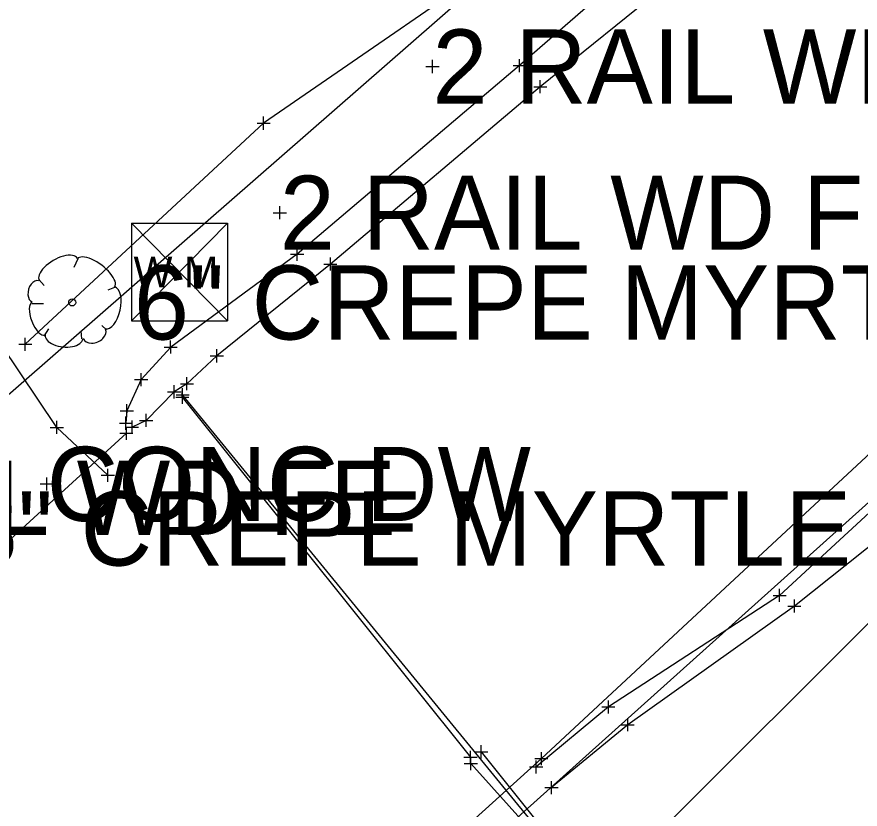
# Model space of a CAD drawing. Extents: x -1 to 1157254, y -1 to 2021979.
# Drawn here: x 1147450.2 to 1147532.2, y 2017383.4 to 2017460.4 of the extents above; entities that cross this region are included whole.
import ezdxf

# ---------------------------------------------------------------- set-up
doc = ezdxf.new("R2010")
doc.units = 0
for name, color, linetype in [('S_BUILDING_ANNOT', 7, 'Continuous'), ('S_CAL_CORNER_ANNOT', 7, 'Continuous'), ('S_CONTOUR_ANNOT', 7, 'Continuous'), ('S_CTL_TABLE', 7, 'Continuous'), ('S_CURB', 7, 'Continuous'), ('S_DITCHLINE', 7, 'Continuous'), ('S_DRIVEWAY_ANNOT', 7, 'Continuous'), ('S_DROP_INLET', 7, 'Continuous'), ('S_DROP_INLET_ANNOT', 7, 'Continuous'), ('S_EDGE_BITUMINOUS_ANNOT', 7, 'Continuous'), ('S_ENV_CONSTRAINT', 7, 'Continuous'), ('S_EXIST_ROW', 7, 'Continuous'), ('S_FENCE', 7, 'Continuous'), ('S_GATE', 7, 'Continuous'), ('S_GATE_ANNOT', 7, 'Continuous')]:
    doc.layers.add(name, color=color, linetype=linetype)

msp = doc.modelspace()

# ---------------------------------------------------------------- linework, layer by layer
at = {"layer": 'S_BUILDING_ANNOT'}
for p, q in [((1147489.991, 2017455.56), (1147491.263, 2017455.563)), ((1147490.628, 2017454.925), (1147490.625, 2017456.198)), ((1147490.627, 2017455.562), (1147490.627, 2017455.562)), ((1147498.452, 2017455.653), (1147499.724, 2017455.656)), ((1147499.089, 2017455.018), (1147499.087, 2017456.291)), ((1147499.088, 2017455.655), (1147499.088, 2017455.655)), ((1147501.104, 2017452.962), (1147501.101, 2017454.235)), ((1147500.466, 2017453.597), (1147501.738, 2017453.6)), ((1147501.102, 2017453.599), (1147501.102, 2017453.599)), ((1147475.788, 2017440.725), (1147475.785, 2017441.997)), ((1147475.15, 2017441.36), (1147476.422, 2017441.362)), ((1147475.786, 2017441.361), (1147475.786, 2017441.361)), ((1147477.48, 2017436.691), (1147477.477, 2017437.963)), ((1147476.842, 2017437.326), (1147478.115, 2017437.328)), ((1147477.478, 2017437.327), (1147477.478, 2017437.327)), ((1147480.702, 2017435.742), (1147480.699, 2017437.014)), ((1147480.064, 2017436.377), (1147481.337, 2017436.379)), ((1147480.7, 2017436.378), (1147480.7, 2017436.378)), ((1147465.183, 2017427.676), (1147465.18, 2017428.949)), ((1147464.546, 2017428.311), (1147465.818, 2017428.314)), ((1147465.182, 2017428.313), (1147465.182, 2017428.313)), ((1147469.669, 2017426.824), (1147469.667, 2017428.097)), ((1147469.032, 2017427.459), (1147470.304, 2017427.462)), ((1147469.668, 2017427.461), (1147469.668, 2017427.461)), ((1147462.312, 2017424.516), (1147462.309, 2017425.789)), ((1147466.764, 2017424.116), (1147466.762, 2017425.389)), ((1147461.674, 2017425.151), (1147462.947, 2017425.154)), ((1147462.311, 2017425.152), (1147462.311, 2017425.152)), ((1147465.522, 2017423.335), (1147465.519, 2017424.608)), ((1147466.127, 2017424.751), (1147467.399, 2017424.754)), ((1147466.763, 2017424.752), (1147466.763, 2017424.752)), ((1147464.885, 2017423.97), (1147466.157, 2017423.973)), ((1147465.521, 2017423.971), (1147465.521, 2017423.971)), ((1147465.705, 2017423.683), (1147466.977, 2017423.686)), ((1147466.315, 2017422.805), (1147466.313, 2017424.078)), ((1147466.342, 2017423.048), (1147466.34, 2017424.321)), ((1147466.341, 2017423.684), (1147466.341, 2017423.684)), ((1147460.925, 2017421.491), (1147460.922, 2017422.764)), ((1147465.678, 2017423.44), (1147466.95, 2017423.443)), ((1147466.314, 2017423.441), (1147466.314, 2017423.441)), ((1147460.287, 2017422.126), (1147461.56, 2017422.129)), ((1147460.924, 2017422.127), (1147460.924, 2017422.127)), ((1147454.117, 2017419.877), (1147454.114, 2017421.15)), ((1147460.835, 2017420.282), (1147460.832, 2017421.555)), ((1147461.427, 2017419.907), (1147461.424, 2017421.18)), ((1147462.163, 2017421.189), (1147463.436, 2017421.192)), ((1147462.801, 2017420.554), (1147462.798, 2017421.827)), ((1147462.8, 2017421.19), (1147462.8, 2017421.19)), ((1147453.479, 2017420.512), (1147454.752, 2017420.515)), ((1147454.115, 2017420.513), (1147454.115, 2017420.513)), ((1147460.197, 2017420.917), (1147461.47, 2017420.92)), ((1147460.789, 2017420.542), (1147462.062, 2017420.545)), ((1147460.834, 2017420.918), (1147460.834, 2017420.918)), ((1147460.882, 2017419.307), (1147460.879, 2017420.58)), ((1147461.426, 2017420.543), (1147461.426, 2017420.543)), ((1147460.244, 2017419.942), (1147461.517, 2017419.945)), ((1147460.881, 2017419.943), (1147460.881, 2017419.943)), ((1147459.072, 2017415.227), (1147459.069, 2017416.499)), ((1147453.136, 2017414.388), (1147453.133, 2017415.66)), ((1147458.434, 2017415.862), (1147459.707, 2017415.865)), ((1147459.071, 2017415.863), (1147459.071, 2017415.863)), ((1147452.498, 2017415.023), (1147453.771, 2017415.026)), ((1147453.134, 2017415.024), (1147453.134, 2017415.024)), ((1147524.366, 2017403.561), (1147524.364, 2017404.834)), ((1147523.729, 2017404.196), (1147525.001, 2017404.199)), ((1147524.365, 2017404.198), (1147524.365, 2017404.198)), ((1147525.162, 2017403.16), (1147526.434, 2017403.163)), ((1147525.799, 2017402.525), (1147525.797, 2017403.798)), ((1147525.798, 2017403.162), (1147525.798, 2017403.162)), ((1147507.085, 2017393.363), (1147508.358, 2017393.366)), ((1147507.723, 2017392.728), (1147507.72, 2017394.001)), ((1147507.721, 2017393.364), (1147507.721, 2017393.364)), ((1147508.962, 2017391.632), (1147510.235, 2017391.635)), ((1147509.6, 2017390.997), (1147509.597, 2017392.27)), ((1147509.598, 2017391.633), (1147509.598, 2017391.633)), ((1147495.364, 2017388.364), (1147495.362, 2017389.636)), ((1147493.687, 2017388.475), (1147494.959, 2017388.477)), ((1147494.324, 2017387.84), (1147494.322, 2017389.112)), ((1147494.323, 2017388.476), (1147494.323, 2017388.476)), ((1147494.35, 2017387.229), (1147494.348, 2017388.501)), ((1147494.727, 2017388.999), (1147495.999, 2017389.002)), ((1147495.363, 2017389), (1147495.363, 2017389)), ((1147500.57, 2017388.345), (1147501.842, 2017388.347)), ((1147501.208, 2017387.71), (1147501.205, 2017388.982)), ((1147501.206, 2017388.346), (1147501.206, 2017388.346)), ((1147493.713, 2017387.864), (1147494.985, 2017387.866)), ((1147494.349, 2017387.865), (1147494.349, 2017387.865)), ((1147500.069, 2017387.534), (1147501.341, 2017387.536)), ((1147500.707, 2017386.899), (1147500.704, 2017388.171)), ((1147500.705, 2017387.535), (1147500.705, 2017387.535)), ((1147502.19, 2017384.889), (1147502.187, 2017386.161)), ((1147501.552, 2017385.524), (1147502.824, 2017385.526)), ((1147502.188, 2017385.525), (1147502.188, 2017385.525))]:
    msp.add_line(p, q, dxfattribs=at)
at = {"layer": 'S_CAL_CORNER_ANNOT'}
msp.add_lwpolyline([(1148176.106, 2017926.044), (1148136.135, 2017895.283), (1148103.217, 2017868.951), (1148054.86, 2017832.593), (1147994.132, 2017784.964), (1147955.313, 2017755.813), (1147823.063, 2017654.265), (1147729.592, 2017581.352), (1147643.019, 2017515.607), (1147594.541, 2017475.046), (1147501.206, 2017388.346), (1147435.286, 2017328.794), (1147395.528, 2017293.456), (1147348.748, 2017254.127), (1147258.659, 2017171.573), (1147166.985, 2017089.787), (1147151.244, 2017076.13), (1147027.412, 2016982.557), (1146975.56, 2016939.412), (1146851.179, 2016835.149), (1146821.227, 2016867.045), (1146788.362, 2016903.205)], dxfattribs=at)
at = {"layer": 'S_CONTOUR_ANNOT'}
for p, q in [((1147461.365, 2017440.341), (1147470.7, 2017440.341)), ((1147461.365, 2017440.341), (1147461.365, 2017430.851)), ((1147461.365, 2017440.341), (1147470.7, 2017430.851)), ((1147470.7, 2017440.341), (1147461.365, 2017430.851)), ((1147470.7, 2017440.341), (1147470.7, 2017430.851)), ((1147461.365, 2017430.851), (1147470.7, 2017430.851))]:
    msp.add_line(p, q, dxfattribs=at)
msp.add_lwpolyline([(1148171.011, 2018007.638), (1148133.816, 2017978.125), (1147884.861, 2017790.184), (1147810.337, 2017733.241), (1147725.213, 2017658.338), (1147638.363, 2017588.802), (1147507.672, 2017474.516), (1147125.41, 2017140.989), (1145970.617, 2016384.057)], dxfattribs=at)
at = {"layer": 'S_CTL_TABLE'}
for p, q in [((1147474.215, 2017449.425), (1147474.212, 2017450.698)), ((1147473.577, 2017450.06), (1147474.849, 2017450.063)), ((1147474.213, 2017450.061), (1147474.213, 2017450.061)), ((1147450.411, 2017428.589), (1147451.684, 2017428.592)), ((1147451.049, 2017427.954), (1147451.046, 2017429.227)), ((1147451.047, 2017428.591), (1147451.047, 2017428.591))]:
    msp.add_line(p, q, dxfattribs=at)
at = {"layer": 'S_CURB'}
for p, q in [((1147456.166, 2017436.891), (1147455.779, 2017436.038)), ((1147452.37, 2017434.876), (1147452.874, 2017434.295)), ((1147459.73, 2017434.102), (1147459.071, 2017433.831)), ((1147451.712, 2017432.552), (1147452.835, 2017432.552)), ((1147458.955, 2017429.996), (1147458.49, 2017430.422)), ((1147452.874, 2017429.376), (1147453.339, 2017430.073)), ((1147456.554, 2017429.105), (1147456.476, 2017429.88))]:
    msp.add_line(p, q, dxfattribs=at)
msp.add_circle((1147455.608, 2017432.647), 0.34, dxfattribs=at)
for centre, major_axis, ratio, start_param, end_param in [((1147454.273, 2017435.848), (1.856, 1.084), 0.471018, 0, 3.141593), ((1147457.926, 2017435.525), (-1.812, 1.359), 0.405113, 3.141593, 6.283186), ((1147452.039, 2017433.734), (0.305, 1.026), 0.646762, 0, 3.141593), ((1147459.281, 2017432.117), (0.458, 2.039), 0.482994, 3.141593, 6.283185), ((1147452.344, 2017431.085), (-0.61, 1.595), 0.420543, 6.283185, 9.424777), ((1147454.804, 2017429.305), (-1.831, 0.194), 0.529943, 0, 3.141593), ((1147457.76, 2017429.597), (1.091, 0.462), 0.711534, 3.141592, 6.283185)]:
    msp.add_ellipse(centre, major_axis=major_axis, ratio=ratio, start_param=start_param, end_param=end_param, dxfattribs=at)
at = {"layer": 'S_DITCHLINE'}
msp.add_lwpolyline([(1147507.986, 2017372.8), (1147466.341, 2017423.684)], dxfattribs=at)
at = {"layer": 'S_DRIVEWAY_ANNOT'}
for points in [[(1147744.553, 2017594.497), (1147743.321, 2017593.742), (1147727.496, 2017582.827), (1147686.458, 2017550.47), (1147642.4, 2017515.309), (1147602.356, 2017485.525), (1147573.623, 2017457.568), (1147547.711, 2017425.718), (1147524.365, 2017404.198), (1147507.721, 2017393.364), (1147500.705, 2017387.535)], [(1147745.212, 2017593.731), (1147744.124, 2017592.133), (1147729.537, 2017581.38), (1147687.377, 2017548.909), (1147643.197, 2017513.751), (1147603.766, 2017484.135), (1147575.104, 2017454.862), (1147550.296, 2017422.653), (1147525.798, 2017403.162), (1147509.598, 2017391.633), (1147502.188, 2017385.525)], [(1147606.428, 2017551.938), (1147604.436, 2017550.182), (1147586.802, 2017533.741), (1147560.835, 2017510.953), (1147533.008, 2017485.021), (1147511.881, 2017466.806), (1147499.088, 2017455.655), (1147477.478, 2017437.327), (1147465.182, 2017428.313), (1147462.311, 2017425.152), (1147460.924, 2017422.127), (1147460.834, 2017420.918)], [(1147606.877, 2017551.33), (1147605.396, 2017549.254), (1147589.008, 2017531.202), (1147563.067, 2017508.054), (1147534.564, 2017482.454), (1147513.62, 2017463.729), (1147501.102, 2017453.599), (1147480.7, 2017436.378), (1147469.668, 2017427.461), (1147466.763, 2017424.752), (1147465.521, 2017423.971), (1147462.8, 2017421.19), (1147461.426, 2017420.543)], [(1147495.363, 2017389), (1147500.93, 2017382.052), (1147512.042, 2017366.501), (1147518.746, 2017352.776), (1147527.164, 2017337.779), (1147526.483, 2017336.046), (1147518.687, 2017327.678), (1147492.008, 2017308.157)], [(1147494.349, 2017387.865), (1147500.088, 2017381.504), (1147511.023, 2017365.799), (1147518.059, 2017352.393), (1147525.687, 2017336.728), (1147517.366, 2017329.292), (1147491.333, 2017308.93)]]:
    msp.add_lwpolyline(points, dxfattribs=at)
at = {"layer": 'S_DROP_INLET'}
msp.add_lwpolyline([(1148195.528, 2017935.768), (1148138.819, 2017892.989), (1148034.426, 2017809.592), (1147909.475, 2017714.316), (1147828.883, 2017654.708), (1147681.29, 2017538.62), (1147545.027, 2017424.01), (1147436.651, 2017326.836), (1147356.287, 2017257.736), (1147237.669, 2017148.836), (1147152.37, 2017082.268), (1147079.411, 2017020.236), (1146950.459, 2016911.581), (1146849.377, 2016826.65), (1146763.176, 2016745.201), (1146663.113, 2016665.755), (1146626.022, 2016634.68), (1146520.536, 2016557.464), (1146484.38, 2016531.034)], dxfattribs=at)
at = {"layer": 'S_DROP_INLET_ANNOT'}
msp.add_lwpolyline([(1147460.881, 2017419.943), (1147446.221, 2017406.592)], dxfattribs=at)
at = {"layer": 'S_EDGE_BITUMINOUS_ANNOT'}
msp.add_lwpolyline([(1147594.685, 2017552.693), (1147563.913, 2017532.816), (1147539.821, 2017509.715), (1147515.64, 2017486.56), (1147501.703, 2017469.001), (1147474.213, 2017450.061), (1147451.047, 2017428.591)], dxfattribs=at)
at = {"layer": 'S_ENV_CONSTRAINT'}
msp.add_lwpolyline([(1147459.071, 2017415.863), (1147454.115, 2017420.513), (1147446.893, 2017431.23), (1147435.232, 2017441.52)], dxfattribs=at)
at = {"layer": 'S_EXIST_ROW'}
msp.add_lwpolyline([(1147466.314, 2017423.441), (1147494.323, 2017388.476)], dxfattribs=at)
at = {"layer": 'S_FENCE'}
msp.add_lwpolyline([(1148182.052, 2017918.064), (1148146.031, 2017882.736), (1148036.878, 2017800.655), (1147915.132, 2017710.899), (1147841.973, 2017653.39), (1147689.753, 2017529.104), (1147550.851, 2017419.327), (1147452.642, 2017321.351), (1147370.713, 2017243.519), (1147258.326, 2017138.296), (1147166.15, 2017078.021), (1147070.177, 2016992.832), (1146962.813, 2016905.873), (1146854.859, 2016827.911), (1146747.328, 2016742.807), (1146665.816, 2016680.994), (1146623.062, 2016638.597), (1146514.264, 2016556.707), (1146391.385, 2016471.398), (1146322.085, 2016427.508), (1146235.838, 2016373.998), (1146176.662, 2016335.007), (1146181.421, 2016326.5)], dxfattribs=at)

# ---------------------------------------------------------------- texts
at = {"layer": 'S_CONTOUR_ANNOT'}
msp.add_text('W M', height=2.9988, dxfattribs=at).set_placement((1147461.57, 2017434.11))
at = {"layer": 'S_GATE'}
for s, p in [('2 RAIL WD FE', (1147490.627, 2017451.962)), ('2 RAIL WD FE', (1147475.786, 2017437.761)), ('CONC DW', (1147453.134, 2017411.424)), ('2 RAIL WD FE', (1147423.943, 2017410.078))]:
    msp.add_text(s, height=7.2, dxfattribs=at).set_placement(p)
at = {"layer": 'S_GATE_ANNOT'}
for s, p in [('6" CREPE MYRTLE', (1147461.608, 2017429.047)), ('8" CREPE MYRTLE', (1147444.97, 2017407.093))]:
    msp.add_text(s, height=7.2, dxfattribs=at).set_placement(p)

doc.saveas('drawing.dxf')
